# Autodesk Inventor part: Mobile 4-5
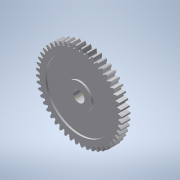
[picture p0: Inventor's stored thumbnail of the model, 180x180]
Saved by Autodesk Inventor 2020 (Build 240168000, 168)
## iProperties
Created: 2002-01
Part Number: Mobile 4-5
Material: Plastique ABS
Document SubType Name: Modélisation
Designer: Philippe
Mass: 0.0624115 g
Surface Area: 2.48188 cm^2
Volume: 0.0588788 cm^3
Density: 1.06 g/cm^3
Appearance: Plastique (Blanc)
Shininess: 21.0
Angle Display Precision: 2
Document Length Units: 11269
Document Angle Units: 11279
Document Time Units: 11290
Document Mass Units: 11283
Document Length Units Precision: 3
Document Angle Units Precision: 2
Density: 0.0
Volumn: 0.0
Area: 0.0
PropertySet Name: Model Information
Control State: 0
Master: False
Checked Out: False
Author: Philippe
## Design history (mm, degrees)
sketch "Esquisse1"
  geometry: L1 (0, 0)-(5, 0); L2 (5, 0)-(5, 1); L3 (5, 1)-(1.5, 1); L4 (1.5, 1)-(1.5, 2.6); L5 (1.5, 2.6)-(0, 2.6); L6 (0, 2.6)-(0, 0)
  constraints: 12 end point, 4 parallel, 1 horizontal, 1 perpendicular, 1 other
  dimensions: "d0" = 1 distance of L1.end L2.end; "d1" = 2.6 distance between parallel lines of L5 L1; "d2" = 3 diameter of L4.end L6; "d3" = 10 diameter of L2 L6
revolve "Révolution1" sketch "Esquisse1" stored, may be unused: angle "d4" = 90 deg
sketch "Esquisse2"
  geometry: C1 r 5 at (0, 0) reference; C2 r 0.65 at (0, 0)
  constraints: 1 centre point, 1 coincident
  dimensions: "d5" = 1.3 diameter of C2
extrude "Extrusion1" cut sketch "Esquisse2" extent not by distance; stored distance "d6" = 10; taper "d7" = 0 deg
node "Axe de construction1"
sketch "Esquisse4"
  geometry: A1 r 4.55 centre (0, 0) between (0.04, 4.55) and (-0.04, 4.55); A2 r 1.642 centre (-1.681, 4.186) between (-0.089, 4.588) and (-0.251, 4.994); A3 r 1.642 centre (1.681, 4.186) between (0.251, 4.994) and (0.089, 4.588); A4 r 0.05 centre (-0.04, 4.6) between (-0.089, 4.588) and (-0.04, 4.55); A5 r 0.05 centre (0.04, 4.6) between (0.04, 4.55) and (0.089, 4.588); A6 r 5 centre (0, 0) between (0.251, 4.994) and (-0.251, 4.994)
  constraints: 12 point on circle, 6 centre point, 4 tangent, 1 equal radius, 3 other
  dimensions: "d18" = 0.05 radius of A4
extrude "Extrusion3" cut sketch "Esquisse4" extent not by distance; stored distance "d19" = 1.3; taper "d20" = 0 deg
sketch "Esquisse5"
  geometry: L1 (0, 0)-(0, 1.285); A1 r 0.825 centre (0, 0) between (0.068, 0.822) and (-0.068, 0.822); A2 r 0.41 centre (-0.585, 0.964) between (-0.176, 0.93) and (-0.602, 1.374); A3 r 0.41 centre (0.585, 0.964) between (0.602, 1.374) and (0.176, 0.93); A4 r 0.1 centre (-0.076, 0.922) between (-0.176, 0.93) and (-0.068, 0.822); A5 r 0.1 centre (0.076, 0.922) between (0.068, 0.822) and (0.176, 0.93); A6 r 1.5 centre (0, 0) between (0.602, 1.374) and (-0.602, 1.374)
  constraints: 12 point on circle, 5 centre point, 4 tangent, 2 end point, 2 symmetric about line, 1 equal radius, 1 vertical, 4 other
  dimensions: "d26" = 0.1 radius of A4
extrude "Extrusion4" cut sketch "Esquisse5" stored distance "d27" = 10; taper "d28" = 0 deg
pattern_circular "Réseau circulaire3" dims angle "d31" = 360 deg
sketch "Esquisse6"
  geometry: C1 r 0.65 at (0.004, 4.511) reference; C2 r 1.5 at (0.004, 4.511); C3 r 3.9 at (0.004, 4.511)
  constraints: 2 centre point
  dimensions: "d32" = 3 diameter of C2; "d33" = 7.8 diameter of C3
extrude "Extrusion5" cut sketch "Esquisse6" distance "d34" = 0.2; taper "d35" = 0 deg
sketch "Esquisse7"
  geometry: C1 r 1.5 at (-0.004, -4.511) reference; C2 r 3.9 at (-0.004, -4.511) reference
extrude "Extrusion6" cut sketch "Esquisse7" distance "d36" = 0.2; taper "d37" = 0 deg
node "Solide1"
node "Corps solides"
node "Corps surfaciques"
pattern_circular "Réseau circulaire2" dims angle "d23" = 360 deg
